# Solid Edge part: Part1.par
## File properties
Author: Robert a Rhodes jr
Template: normal.par
Last saved by: MYPC
Revision: 3
Application: Solid Edge
Density: 0 kg/mm^3
Accuracy: 0.99
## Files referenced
..\Asm2.asm
8D:\solid-edge-16\c09-sld-edg-16-101104\parallel\Asm2.asm
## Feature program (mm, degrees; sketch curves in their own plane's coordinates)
sketch for "unnamed Protrusion 1" #1 plane through (0, 0, 0) normal (0, 0, 1) x-axis (1, 0, 0)
  line (-53.424, 13.2886) -> (-4.9489, 23.498)
  arc centre (0, 0) radius 24.0135 from (-4.9489, 23.498) to (4.9424, 23.4994) cw
  line (4.9424, 23.4994) -> (57.7581, 12.3911)
  arc centre (55.152, 0) radius 12.6622 from (57.7581, 12.3911) to (57.7581, -12.3911) cw
  line (57.7581, -12.3911) -> (4.9424, -23.4994)
  arc centre (0, 0) radius 24.0135 from (4.9424, -23.4994) to (-4.9489, -23.498) cw
  line (-53.424, -13.2886) -> (-4.9489, -23.498)
  arc centre (-50.6253, 0) radius 13.5802 from (-53.424, -13.2886) to (-53.424, 13.2886) cw
sketch for "unnamed Protrusion 1" #2 plane through (0, 0, 0) normal (0, 0, 1) x-axis (1, 0, 0)
  circle centre (-50.6253, 0) radius 7
sketch for "unnamed Protrusion 1" #3 plane through (0, 0, 0) normal (0, 0, 1) x-axis (1, 0, 0)
  circle centre (54.576, 0) radius 7
extrude "unnamed Protrusion 1" add finite 12.7 symmetric
sketch for "ExtrudedProtrusion_2" plane through (1.8044, 0, 12.7) normal (0, 0, 1) x-axis (0.97859, 0.205819, 0)
  circle centre (-1.7657, 0.3714) radius 14.0039
extrude "ExtrudedProtrusion_2" add through along -normal  Plane_Distance = 6.35 mm
sketch for "Hole_1" plane through (0, 0, 12.7) normal (0, 0, 1) x-axis (0, 1, 0)
  hole centre (0, 0) bore radius 9
hole "Hole_1" diameter 18 through
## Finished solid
Body 1: solid body, 15 faces, 32 edges, 16 vertices.
  Faces by surface: cylinder 8, plane 7
  Edges by curve: circle 16, line 16
Bounding box of the edges (mm): 132.020 x 48.027 x 19.050, from (-64.2054, -24.0135, -6.35) to (67.8142, 24.0135, 12.7).
Cylindrical faces by radius (mm): R7 x2, R9 x1, R12.6622 x1, R13.5802 x1, R14.0039 x1, R24.0135 x2
Planar faces by outward normal: +z 2, -z 1, oblique 4
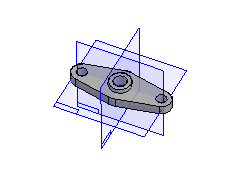
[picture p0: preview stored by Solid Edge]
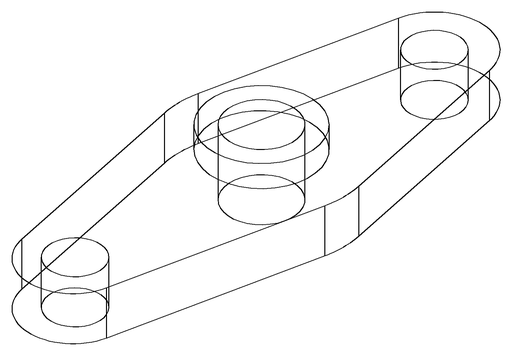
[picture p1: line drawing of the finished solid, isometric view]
